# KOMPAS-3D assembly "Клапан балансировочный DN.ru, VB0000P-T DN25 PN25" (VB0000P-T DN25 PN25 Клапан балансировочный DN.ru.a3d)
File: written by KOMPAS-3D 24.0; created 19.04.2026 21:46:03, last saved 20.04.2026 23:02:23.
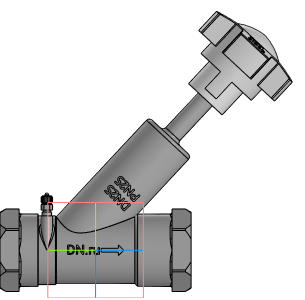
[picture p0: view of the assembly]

Document properties: Автор: DN.ru; Полное имя файла: C:\Работа\VB0000P-T DN X PN 25 Клапан балансировочный DN.ru\DN25\исходные материалы\VB0000P-T DN25 PN25 Клапан балансировочный DN.ru.a3d

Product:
- Component [detail]: Деталь  | qty 1  | pos. 1  | Масса: 0.00084; Раздел спецификации: Прочие изделия; Примечание: D080-01177; Автор: mrdid; source file: VB0000P-T DN25 PN25 Клапан балансировочный DN.ru.m3d
- Component [detail]: Деталь2  | qty 1  | pos. 2  | Масса: 0.358794; Автор: tyuri; additional columns: Типовые; source file: Деталь2 - Деталь2.m3d
- Part/product: Клапан балансировочный DN.ru  | designation VB0000P-T DN25 PN25
    Масса: 0.84
    Раздел спецификации: Прочие изделия
    Примечание: D080-01177

Referenced files in C:\Работа\VB0000P-T DN X PN 25 Клапан балансировочный DN.ru\DN25\исходные материалы\: Деталь2 - Деталь2.m3d, VB0000P-T DN25 PN25 Клапан балансировочный DN.ru.m3d
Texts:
  VB0000P-T DN25 PN25
  Деталь2 Деталь2
  Плоскость XY.Начало координат
  Плоскость ZY.Начало координат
